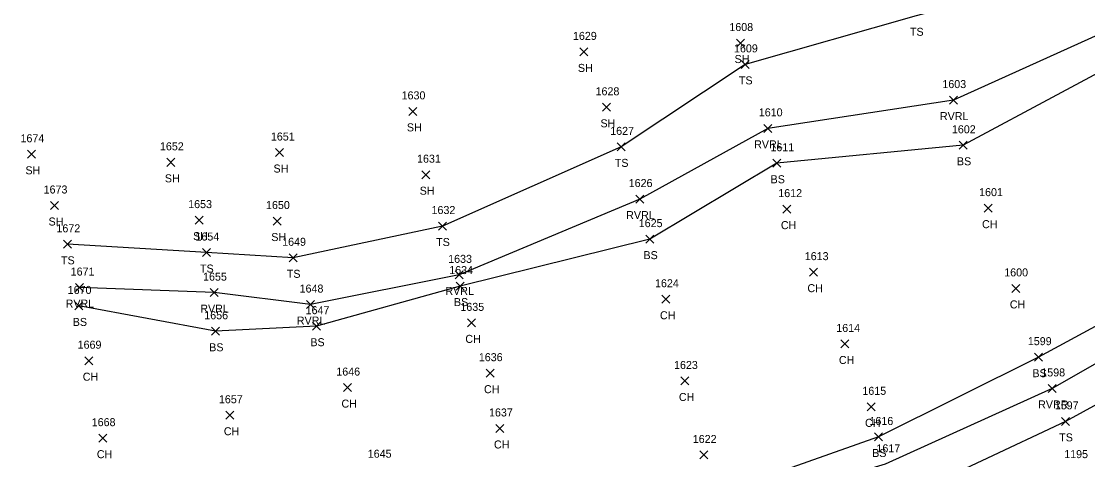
# Model space of a CAD drawing. Extents: x 1443064 to 1445163, y 544063 to 544655.
# Drawn here: x 1443065.5 to 1443332.1, y 544274.6 to 544384.1 of the extents above; entities that cross this region are included whole.
import ezdxf

# ---------------------------------------------------------------- set-up
doc = ezdxf.new("R2010")
doc.units = 0
for name, color, linetype in [('L_A', 7, 'Continuous'), ('L_I', 7, 'Continuous'), ('L_TIC', 7, 'Continuous'), ('LAWE', 7, 'Continuous'), ('LELB', 7, 'Continuous')]:
    doc.layers.add(name, color=color, linetype=linetype)

msp = doc.modelspace()

# ---------------------------------------------------------------- linework, layer by layer
at = {"layer": 'L_TIC'}
for points in [[(1443244.33, 544377.71), (1443246.33, 544379.71)], [(1443246.33, 544377.71), (1443244.33, 544379.71)], [(1443205.17, 544375.5), (1443207.17, 544377.5)], [(1443207.17, 544375.5), (1443205.17, 544377.5)], [(1443245.49, 544372.38), (1443247.49, 544374.38)], [(1443247.49, 544372.38), (1443245.49, 544374.38)], [(1443297.57, 544363.46), (1443299.57, 544365.46)], [(1443299.57, 544363.46), (1443297.57, 544365.46)], [(1443162.42, 544360.64), (1443164.42, 544362.64)], [(1443164.42, 544360.64), (1443162.42, 544362.64)], [(1443210.81, 544361.66), (1443212.81, 544363.66)], [(1443212.81, 544361.66), (1443210.81, 544363.66)], [(1443251.13, 544356.4), (1443253.13, 544358.4)], [(1443253.13, 544356.4), (1443251.13, 544358.4)], [(1443067.08, 544349.92), (1443069.08, 544351.92)], [(1443069.08, 544349.92), (1443067.08, 544351.92)], [(1443129.1, 544350.36), (1443131.1, 544352.36)], [(1443131.1, 544350.36), (1443129.1, 544352.36)], [(1443214.47, 544351.77), (1443216.47, 544353.77)], [(1443216.47, 544351.77), (1443214.47, 544353.77)], [(1443299.95, 544352.17), (1443301.95, 544354.17)], [(1443301.95, 544352.17), (1443299.95, 544354.17)], [(1443101.93, 544347.91), (1443103.93, 544349.91)], [(1443103.93, 544347.91), (1443101.93, 544349.91)], [(1443253.38, 544347.68), (1443255.38, 544349.68)], [(1443255.38, 544347.68), (1443253.38, 544349.68)], [(1443165.62, 544344.82), (1443167.62, 544346.82)], [(1443167.62, 544344.82), (1443165.62, 544346.82)], [(1443072.86, 544337.12), (1443074.86, 544339.12)], [(1443074.86, 544337.12), (1443072.86, 544339.12)], [(1443219.15, 544338.73), (1443221.15, 544340.73)], [(1443221.15, 544338.73), (1443219.15, 544340.73)], [(1443306.18, 544336.46), (1443308.18, 544338.46)], [(1443308.18, 544336.46), (1443306.18, 544338.46)], [(1443255.91, 544336.22), (1443257.91, 544338.22)], [(1443257.91, 544336.22), (1443255.91, 544338.22)], [(1443108.99, 544333.47), (1443110.99, 544335.47)], [(1443110.99, 544333.47), (1443108.99, 544335.47)], [(1443128.53, 544333.24), (1443130.53, 544335.24)], [(1443130.53, 544333.24), (1443128.53, 544335.24)], [(1443169.81, 544331.99), (1443171.81, 544333.99)], [(1443171.81, 544331.99), (1443169.81, 544333.99)], [(1443221.6, 544328.72), (1443223.6, 544330.72)], [(1443223.6, 544328.72), (1443221.6, 544330.72)], [(1443076.06, 544327.43), (1443078.06, 544329.43)], [(1443078.06, 544327.43), (1443076.06, 544329.43)], [(1443110.8, 544325.37), (1443112.8, 544327.37)], [(1443112.8, 544325.37), (1443110.8, 544327.37)], [(1443132.49, 544324.06), (1443134.49, 544326.06)], [(1443134.49, 544324.06), (1443132.49, 544326.06)], [(1443262.53, 544320.47), (1443264.53, 544322.47)], [(1443264.53, 544320.47), (1443262.53, 544322.47)], [(1443173.97, 544319.79), (1443175.97, 544321.79)], [(1443175.97, 544319.79), (1443173.97, 544321.79)], [(1443079.05, 544316.62), (1443081.05, 544318.62)], [(1443081.05, 544316.62), (1443079.05, 544318.62)], [(1443112.71, 544315.35), (1443114.71, 544317.35)], [(1443114.71, 544315.35), (1443112.71, 544317.35)], [(1443174.23, 544316.99), (1443176.23, 544318.99)], [(1443176.23, 544316.99), (1443174.23, 544318.99)], [(1443313.12, 544316.41), (1443315.12, 544318.41)], [(1443315.12, 544316.41), (1443313.12, 544318.41)], [(1443225.67, 544313.7), (1443227.67, 544315.7)], [(1443227.67, 544313.7), (1443225.67, 544315.7)], [(1443078.96, 544312.03), (1443080.96, 544314.03)], [(1443080.96, 544312.03), (1443078.96, 544314.03)], [(1443136.84, 544312.37), (1443138.84, 544314.37)], [(1443138.84, 544312.37), (1443136.84, 544314.37)], [(1443177.02, 544307.8), (1443179.02, 544309.8)], [(1443179.02, 544307.8), (1443177.02, 544309.8)], [(1443113.07, 544305.7), (1443115.07, 544307.7)], [(1443115.07, 544305.7), (1443113.07, 544307.7)], [(1443138.34, 544306.97), (1443140.34, 544308.97)], [(1443140.34, 544306.97), (1443138.34, 544308.97)], [(1443270.41, 544302.53), (1443272.41, 544304.53)], [(1443272.41, 544302.53), (1443270.41, 544304.53)], [(1443318.81, 544299.23), (1443320.81, 544301.23)], [(1443320.81, 544299.23), (1443318.81, 544301.23)], [(1443081.41, 544298.35), (1443083.41, 544300.35)], [(1443083.41, 544298.35), (1443081.41, 544300.35)], [(1443181.69, 544295.23), (1443183.69, 544297.23)], [(1443183.69, 544295.23), (1443181.69, 544297.23)], [(1443146.07, 544291.63), (1443148.07, 544293.63)], [(1443148.07, 544291.63), (1443146.07, 544293.63)], [(1443230.42, 544293.28), (1443232.42, 544295.28)], [(1443232.42, 544293.28), (1443230.42, 544295.28)], [(1443322.16, 544291.42), (1443324.16, 544293.42)], [(1443324.16, 544291.42), (1443322.16, 544293.42)], [(1443276.92, 544286.82), (1443278.92, 544288.82)], [(1443278.92, 544286.82), (1443276.92, 544288.82)], [(1443116.67, 544284.72), (1443118.67, 544286.72)], [(1443118.67, 544284.72), (1443116.67, 544286.72)], [(1443325.54, 544283.19), (1443327.54, 544285.19)], [(1443327.54, 544283.19), (1443325.54, 544285.19)], [(1443184.18, 544281.42), (1443186.18, 544283.42)], [(1443186.18, 544281.42), (1443184.18, 544283.42)], [(1443084.93, 544278.99), (1443086.93, 544280.99)], [(1443086.93, 544278.99), (1443084.93, 544280.99)], [(1443278.76, 544279.29), (1443280.76, 544281.29)], [(1443280.76, 544279.29), (1443278.76, 544281.29)], [(1443235.1, 544274.79), (1443237.1, 544276.79)], [(1443237.1, 544274.79), (1443235.1, 544276.79)]]:
    msp.add_lwpolyline(points, dxfattribs=at)
at = {"layer": 'LAWE'}
for points in [[(1443607.93, 544544.59), (1443575.82, 544505.29), (1443541.97, 544483.15), (1443496.37, 544455.19), (1443456.91, 544428.49), (1443417.34, 544408.78), (1443387.79, 544395.13), (1443348.53, 544386.99), (1443298.57, 544364.46), (1443252.13, 544357.4), (1443220.15, 544339.73), (1443174.97, 544320.79), (1443137.84, 544313.37), (1443113.71, 544316.35), (1443080.05, 544317.62)], [(1443627.73, 544516.96), (1443602.93, 544465.06), (1443560.09, 544445.87), (1443514.11, 544419.1), (1443476.33, 544389.4), (1443439.4, 544357.75), (1443402.97, 544339.11), (1443368.14, 544318.06), (1443323.16, 544292.42), (1443281.44, 544273.46), (1443240.37, 544261.14), (1443193.33, 544260.65), (1443164.34, 544237.83), (1443139.78, 544220.74), (1443138.28, 544217.17), (1443133.77, 544210.32), (1443100.97, 544202.05)]]:
    msp.add_lwpolyline(points, dxfattribs=at)
at = {"layer": 'LELB'}
for points in [[(1443603.25, 544552.64), (1443570.25, 544515.22), (1443538.04, 544489.77), (1443492.2, 544462.32), (1443452.76, 544437.41), (1443412.31, 544422.78), (1443382, 544406.31), (1443343.94, 544400.11), (1443289.24, 544385.53), (1443246.49, 544373.38), (1443215.47, 544352.77), (1443170.81, 544332.99), (1443133.49, 544325.06), (1443111.8, 544326.37), (1443077.06, 544328.43)], [(1443612.67, 544538.44), (1443580.84, 544497.81), (1443546.17, 544475.2), (1443499.76, 544448.59), (1443458.28, 544425.05), (1443417.94, 544404), (1443390.54, 544385.82), (1443350.07, 544379.5), (1443300.95, 544353.17), (1443254.38, 544348.68), (1443222.6, 544329.72), (1443175.23, 544317.99), (1443139.34, 544307.97), (1443114.07, 544306.7), (1443079.96, 544313.03)], [(1443623.25, 544521.72), (1443599.67, 544467.52), (1443557.8, 544451.16), (1443512.32, 544424.47), (1443473.97, 544391.39), (1443436.99, 544360.77), (1443402.58, 544340.48), (1443365.21, 544324.82), (1443319.81, 544300.23), (1443279.76, 544280.29), (1443239.01, 544265.94), (1443191.15, 544266.77), (1443161, 544250.15), (1443130.5, 544221.16), (1443098.72, 544215.41)], [(1443630.6, 544513.66), (1443606.19, 544459.79), (1443563.47, 544440.26), (1443516.58, 544414.23), (1443479.57, 544386.27), (1443441.49, 544354.15), (1443406.03, 544333.57), (1443372.48, 544309.35), (1443326.54, 544284.19), (1443284.74, 544264.48), (1443242.9, 544256.57), (1443195.74, 544252.68), (1443182.88, 544237.49), (1443172.34, 544228.16)]]:
    msp.add_lwpolyline(points, dxfattribs=at)

# ---------------------------------------------------------------- texts
at = {"layer": 'L_A'}
for s, p in [('TS', (1443287.65, 544380.53)), ('SH', (1443243.81, 544373.71)), ('SH', (1443204.65, 544371.5)), ('TS', (1443244.9, 544368.38)), ('RVRL', (1443295.14, 544359.46)), ('SH', (1443161.91, 544356.64)), ('SH', (1443210.29, 544357.66)), ('RVRL', (1443248.7, 544352.4)), ('TS', (1443213.88, 544347.77)), ('BS', (1443299.39, 544348.17)), ('SH', (1443066.57, 544345.92)), ('SH', (1443128.58, 544346.36)), ('SH', (1443101.42, 544343.91)), ('BS', (1443252.82, 544343.68)), ('SH', (1443165.11, 544340.82)), ('RVRL', (1443216.72, 544334.73)), ('SH', (1443072.35, 544333.12)), ('CH', (1443255.39, 544332.22)), ('CH', (1443305.67, 544332.46)), ('SH', (1443108.48, 544329.47)), ('SH', (1443128.02, 544329.24)), ('TS', (1443169.22, 544327.99)), ('TS', (1443075.47, 544323.43)), ('BS', (1443221.04, 544324.72)), ('TS', (1443110.21, 544321.37)), ('TS', (1443131.9, 544320.06)), ('RVRL', (1443171.54, 544315.79)), ('CH', (1443262.02, 544316.47)), ('RVRL', (1443076.62, 544312.62)), ('BS', (1443173.67, 544312.99)), ('CH', (1443312.61, 544312.41)), ('RVRL', (1443110.28, 544311.35)), ('BS', (1443078.4, 544308.03)), ('RVRL', (1443134.4, 544308.37)), ('CH', (1443225.16, 544309.7)), ('BS', (1443137.79, 544302.97)), ('CH', (1443176.51, 544303.8)), ('BS', (1443112.51, 544301.7)), ('CH', (1443269.89, 544298.53)), ('CH', (1443080.9, 544294.35)), ('BS', (1443318.25, 544295.23)), ('CH', (1443181.18, 544291.23)), ('CH', (1443229.9, 544289.28)), ('CH', (1443145.56, 544287.63)), ('RVRR', (1443319.68, 544287.42)), ('CH', (1443116.16, 544280.72)), ('CH', (1443276.41, 544282.82)), ('TS', (1443324.95, 544279.19)), ('CH', (1443183.67, 544277.42)), ('BS', (1443278.2, 544275.29)), ('CH', (1443084.42, 544274.99))]:
    msp.add_text(s, height=2, dxfattribs=at).set_placement(p)
at = {"layer": 'L_I'}
for s, p in [('1608', (1443242.51, 544381.71)), ('1629', (1443203.42, 544379.5)), ('1609', (1443243.67, 544376.38)), ('1603', (1443295.75, 544367.46)), ('1630', (1443160.59, 544364.64)), ('1628', (1443209.07, 544365.66)), ('1610', (1443249.87, 544360.4)), ('1627', (1443212.73, 544355.77)), ('1602', (1443298.13, 544356.17)), ('1674', (1443065.34, 544353.92)), ('1651', (1443127.92, 544354.36)), ('1652', (1443100.19, 544351.91)), ('1611', (1443252.77, 544351.68)), ('1631', (1443164.45, 544348.82)), ('1626', (1443217.35, 544342.73)), ('1673', (1443071.12, 544341.12)), ('1612', (1443254.73, 544340.22)), ('1601', (1443304.93, 544340.46)), ('1653', (1443107.25, 544337.47)), ('1650', (1443126.7, 544337.24)), ('1632', (1443168.07, 544335.99)), ('1672', (1443074.32, 544331.43)), ('1625', (1443219.86, 544332.72)), ('1654', (1443109.06, 544329.37)), ('1649', (1443130.74, 544328.06)), ('1633', (1443172.23, 544323.79)), ('1613', (1443261.36, 544324.47)), ('1671', (1443077.88, 544320.62)), ('1634', (1443172.49, 544320.99)), ('1600', (1443311.21, 544320.41)), ('1655', (1443110.97, 544319.35)), ('1670', (1443077.13, 544316.03)), ('1648', (1443135.1, 544316.37)), ('1624', (1443223.93, 544317.7)), ('1647', (1443136.6, 544310.97)), ('1635', (1443175.28, 544311.8)), ('1656', (1443111.27, 544309.7)), ('1614', (1443269.23, 544306.53)), ('1669', (1443079.62, 544302.35)), ('1599', (1443317.11, 544303.23)), ('1636', (1443179.89, 544299.23)), ('1623', (1443228.68, 544297.28)), ('1646', (1443144.27, 544295.63)), ('1598', (1443320.47, 544295.42)), ('1657', (1443114.93, 544288.72)), ('1615', (1443275.75, 544290.82)), ('1597', (1443323.85, 544287.19)), ('1637', (1443182.44, 544285.42)), ('1616', (1443277.53, 544283.29)), ('1668', (1443083.14, 544282.99)), ('1622', (1443233.36, 544278.79)), ('1645', (1443152.13, 544275.11)), ('1617', (1443279.27, 544276.46)), ('1195', (1443326.2, 544275.01))]:
    msp.add_text(s, height=2, dxfattribs=at).set_placement(p)

doc.saveas('drawing.dxf')
